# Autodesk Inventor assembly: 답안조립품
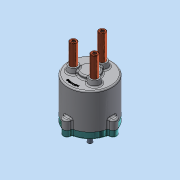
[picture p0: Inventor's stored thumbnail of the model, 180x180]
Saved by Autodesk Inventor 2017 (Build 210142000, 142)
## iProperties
Part Number: 답안조립품
Material: 일반
Document SubType Name: Assembly
Designer: MRC
Mass: 1236.63 g
Surface Area: 1770.13 cm^2
Volume: 433.788 cm^3
Density: 2.85078 g/cm^3
Author: MRC
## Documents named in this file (14)
- C:\Users\MRC\Desktop\610708V1006\답안조립품.iam
- C:\Users\MRC\Desktop\610708V1006\본체.ipt
- C:\Users\MRC\Desktop\610708V1006\가변스프링1.ipt
- C:\Users\MRC\Desktop\610708V1006\가변스프링2.ipt
- C:\Users\MRC\Desktop\610708V1006\가변스프링3.ipt
- C:\Users\MRC\Desktop\610708V1006\멈춤링 10 x 1.ipt
- C:\Users\MRC\Desktop\610708V1006\멈춤링 22 x 1.2.ipt
- C:\Users\MRC\Desktop\610708V1006\메인 축.ipt
- C:\Users\MRC\Desktop\610708V1006\베어링 NA 4900.ipt
- C:\Users\MRC\Desktop\610708V1006\볼트 M5.ipt
- C:\Users\MRC\Desktop\610708V1006\슬라이드 축.ipt
- C:\Users\MRC\Desktop\610708V1006\오일실.ipt
- C:\Users\MRC\Desktop\610708V1006\커버.ipt
- C:\Users\MRC\Desktop\610708V1006\판캠.ipt
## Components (3 placed, 3 different names)
1. 가변스프링1:1
2. 가변스프링2:1
3. 가변스프링3:1
